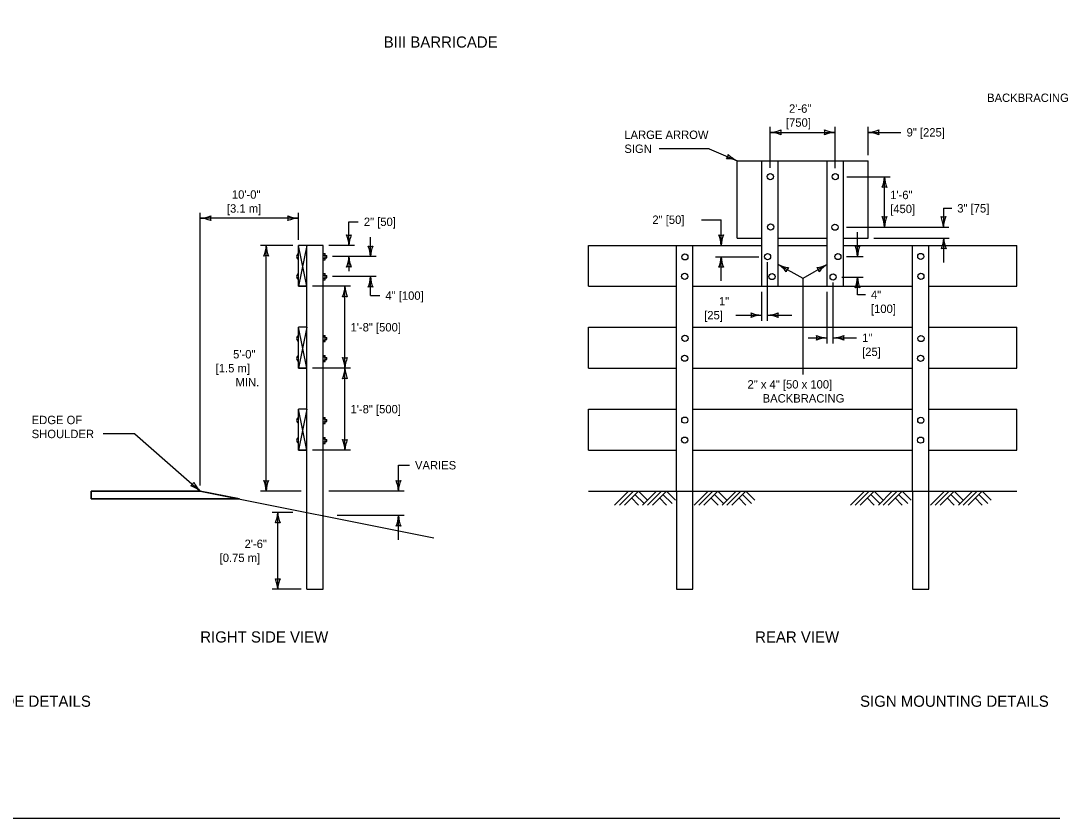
# Model space of a CAD drawing. Extents: x 49991.4 to 50021, y 49987.6 to 50011.4.
# Drawn here: x 50003.93 to 50011.31, y 49987.8 to 49993.51 of the extents above; entities that cross this region are included whole.
import ezdxf

# ---------------------------------------------------------------- set-up
doc = ezdxf.new("R2010")
doc.units = 0
for name, color, linetype in [('Level 1', 7, 'Continuous'), ('Level 2', 7, 'Continuous'), ('Level 3', 7, 'Continuous'), ('Level 4', 7, 'Continuous')]:
    doc.layers.add(name, color=color, linetype=linetype)

msp = doc.modelspace()

# ---------------------------------------------------------------- linework, layer by layer
at = {"layer": 'Level 1'}
for p, q in [((50009.0542, 49992.5038), (50009.9916, 49992.5038)), ((50009.0542, 49991.95), (50009.0542, 49992.5038)), ((50009.2301, 49991.6053), (50009.2301, 49992.5038)), ((50009.3472, 49991.6053), (50009.3472, 49992.5038)), ((50009.6988, 49991.6053), (50009.6988, 49992.5038)), ((50009.8159, 49991.6053), (50009.8159, 49992.5038)), ((50009.9916, 49991.95), (50009.9916, 49992.5038)), ((50009.0542, 49991.95), (50009.2301, 49991.95)), ((50009.3472, 49991.95), (50009.6988, 49991.95)), ((50009.8159, 49991.95), (50009.9916, 49991.95)), ((50005.919, 49991.6053), (50005.919, 49991.8982)), ((50005.9778, 49991.6053), (50005.919, 49991.8982)), ((50005.9778, 49991.8982), (50005.919, 49991.6053)), ((50006.0949, 49991.8982), (50005.919, 49991.8982)), ((50005.9778, 49989.9884), (50005.9778, 49991.8982)), ((50006.0949, 49989.9649), (50006.0949, 49991.8982)), ((50007.991, 49991.8982), (50009.2301, 49991.8982)), ((50007.991, 49991.6053), (50007.991, 49991.8982)), ((50008.6205, 49990.1408), (50008.6205, 49991.8982)), ((50008.7376, 49990.1408), (50008.7376, 49991.8982)), ((50009.3472, 49991.8982), (50009.6988, 49991.8982)), ((50009.8159, 49991.8982), (50011.0547, 49991.8982)), ((50010.308, 49990.1408), (50010.308, 49991.8982)), ((50010.4251, 49990.1408), (50010.4251, 49991.8982)), ((50011.0547, 49991.6053), (50011.0547, 49991.8982)), ((50006.0949, 49991.8397), (50006.1099, 49991.8397)), ((50006.0949, 49991.8287), (50006.1099, 49991.8287)), ((50006.0949, 49991.8067), (50006.1099, 49991.8067)), ((50006.1099, 49991.7957), (50006.1099, 49991.8397)), ((50006.1099, 49991.8252), (50006.1213, 49991.8252)), ((50006.1099, 49991.8102), (50006.1213, 49991.8102)), ((50006.1213, 49991.8102), (50006.1213, 49991.8252)), ((50006.0949, 49991.7957), (50006.1099, 49991.7957)), ((50006.0949, 49991.6966), (50006.1099, 49991.6966)), ((50006.0949, 49991.6856), (50006.1099, 49991.6856)), ((50006.0949, 49991.6636), (50006.1099, 49991.6636)), ((50006.1099, 49991.6526), (50006.1099, 49991.6966)), ((50006.1099, 49991.6821), (50006.1213, 49991.6821)), ((50006.1099, 49991.6671), (50006.1213, 49991.6671)), ((50006.1213, 49991.6671), (50006.1213, 49991.6821)), ((50005.919, 49991.6053), (50005.9778, 49991.6053)), ((50005.9778, 49991.6053), (50005.919, 49991.6053)), ((50006.0949, 49991.6526), (50006.1099, 49991.6526)), ((50007.991, 49991.6053), (50008.6205, 49991.6053)), ((50008.7376, 49991.6053), (50010.308, 49991.6053)), ((50010.4251, 49991.6053), (50011.0547, 49991.6053)), ((50005.919, 49991.0195), (50005.919, 49991.3124)), ((50005.9778, 49991.0195), (50005.919, 49991.3124)), ((50005.9778, 49991.3124), (50005.919, 49991.0195)), ((50005.9778, 49991.3124), (50005.919, 49991.3124)), ((50007.991, 49991.3124), (50008.6205, 49991.3124)), ((50007.991, 49991.0195), (50007.991, 49991.3124)), ((50008.7376, 49991.3124), (50010.308, 49991.3124)), ((50010.4251, 49991.3124), (50011.0547, 49991.3124)), ((50011.0547, 49991.0195), (50011.0547, 49991.3124)), ((50006.0949, 49991.2539), (50006.1099, 49991.2539)), ((50006.0949, 49991.2429), (50006.1099, 49991.2429)), ((50006.0949, 49991.2209), (50006.1099, 49991.2209)), ((50006.1099, 49991.2099), (50006.1099, 49991.2539)), ((50006.1099, 49991.2394), (50006.1213, 49991.2394)), ((50006.1099, 49991.2244), (50006.1213, 49991.2244)), ((50006.1213, 49991.2244), (50006.1213, 49991.2394)), ((50006.0949, 49991.2099), (50006.1099, 49991.2099)), ((50006.0949, 49991.1108), (50006.1099, 49991.1108)), ((50006.0949, 49991.0998), (50006.1099, 49991.0998)), ((50006.0949, 49991.0778), (50006.1099, 49991.0778)), ((50006.0949, 49991.0668), (50006.1099, 49991.0668)), ((50006.1099, 49991.0668), (50006.1099, 49991.1108)), ((50006.1099, 49991.0963), (50006.1213, 49991.0963)), ((50006.1099, 49991.0813), (50006.1213, 49991.0813)), ((50006.1213, 49991.0813), (50006.1213, 49991.0963)), ((50005.919, 49991.0195), (50005.9778, 49991.0195)), ((50005.9778, 49991.0195), (50005.919, 49991.0195)), ((50007.991, 49991.0195), (50008.6205, 49991.0195)), ((50008.7376, 49991.0195), (50010.308, 49991.0195)), ((50010.4251, 49991.0195), (50011.0547, 49991.0195)), ((50005.919, 49990.4336), (50005.919, 49990.7265)), ((50005.9778, 49990.4336), (50005.919, 49990.7265)), ((50005.9778, 49990.7265), (50005.919, 49990.4336)), ((50005.9778, 49990.7265), (50005.919, 49990.7265)), ((50007.991, 49990.7265), (50008.6205, 49990.7265)), ((50007.991, 49990.4336), (50007.991, 49990.7265)), ((50008.7376, 49990.7265), (50010.308, 49990.7265)), ((50010.4251, 49990.7265), (50011.0547, 49990.7265)), ((50011.0547, 49990.4336), (50011.0547, 49990.7265)), ((50006.0949, 49990.668), (50006.1099, 49990.668)), ((50006.0949, 49990.657), (50006.1099, 49990.657)), ((50006.0949, 49990.635), (50006.1099, 49990.635)), ((50006.0949, 49990.624), (50006.1099, 49990.624)), ((50006.1099, 49990.624), (50006.1099, 49990.668)), ((50006.1099, 49990.6535), (50006.1213, 49990.6535)), ((50006.1099, 49990.6385), (50006.1213, 49990.6385)), ((50006.1213, 49990.6385), (50006.1213, 49990.6535)), ((50006.0949, 49990.5249), (50006.1099, 49990.5249)), ((50006.0949, 49990.5139), (50006.1099, 49990.5139)), ((50006.0949, 49990.4919), (50006.1099, 49990.4919)), ((50006.0949, 49990.4809), (50006.1099, 49990.4809)), ((50006.1099, 49990.4809), (50006.1099, 49990.5249)), ((50006.1099, 49990.5104), (50006.1213, 49990.5104)), ((50006.1099, 49990.4954), (50006.1213, 49990.4954)), ((50006.1213, 49990.4954), (50006.1213, 49990.5104)), ((50005.919, 49990.4336), (50005.9778, 49990.4336)), ((50005.9778, 49990.4336), (50005.919, 49990.4336)), ((50007.991, 49990.4336), (50008.6205, 49990.4336)), ((50008.7376, 49990.4336), (50010.308, 49990.4336)), ((50010.4251, 49990.4336), (50011.0547, 49990.4336)), ((50004.4372, 49990.0846), (50004.4372, 49990.1408)), ((50004.4372, 49990.1408), (50005.2159, 49990.1408)), ((50005.2159, 49990.1408), (50004.4372, 49990.1408)), ((50004.4372, 49990.1408), (50004.4372, 49990.0846)), ((50005.2159, 49990.1408), (50006.8865, 49989.8066)), ((50005.4968, 49990.0846), (50005.2159, 49990.1408)), ((50007.991, 49990.1408), (50011.0547, 49990.1408)), ((50008.1785, 49990.0408), (50008.2785, 49990.1408)), ((50008.2135, 49990.0408), (50008.3135, 49990.1408)), ((50008.2485, 49990.0408), (50008.3485, 49990.1408)), ((50008.3238, 49990.1161), (50008.3888, 49990.0511)), ((50008.3485, 49990.1408), (50008.4135, 49990.0758)), ((50008.3785, 49990.0408), (50008.4785, 49990.1408)), ((50008.4135, 49990.0408), (50008.5135, 49990.1408)), ((50008.4485, 49990.0408), (50008.5485, 49990.1408)), ((50008.5238, 49990.1161), (50008.5888, 49990.0511)), ((50008.5485, 49990.1408), (50008.6135, 49990.0758)), ((50008.7466, 49990.0408), (50008.8466, 49990.1408)), ((50008.7816, 49990.0408), (50008.8816, 49990.1408)), ((50008.8166, 49990.0408), (50008.9166, 49990.1408)), ((50008.8919, 49990.1161), (50008.9569, 49990.0511)), ((50008.9166, 49990.1408), (50008.9816, 49990.0758)), ((50008.9466, 49990.0408), (50009.0466, 49990.1408)), ((50008.9816, 49990.0408), (50009.0816, 49990.1408)), ((50009.0166, 49990.0408), (50009.1166, 49990.1408)), ((50009.0919, 49990.1161), (50009.1569, 49990.0511)), ((50009.1166, 49990.1408), (50009.1816, 49990.0758)), ((50009.8639, 49990.0408), (50009.9639, 49990.1408)), ((50009.8989, 49990.0408), (50009.9989, 49990.1408)), ((50009.9339, 49990.0408), (50010.0339, 49990.1408)), ((50010.0092, 49990.1161), (50010.0742, 49990.0511)), ((50010.0339, 49990.1408), (50010.0989, 49990.0758)), ((50010.0639, 49990.0408), (50010.1639, 49990.1408)), ((50010.0989, 49990.0408), (50010.1989, 49990.1408)), ((50010.1339, 49990.0408), (50010.2339, 49990.1408)), ((50010.2092, 49990.1161), (50010.2742, 49990.0511)), ((50010.2339, 49990.1408), (50010.2989, 49990.0758)), ((50010.4361, 49990.0408), (50010.5361, 49990.1408)), ((50010.4711, 49990.0408), (50010.5711, 49990.1408)), ((50010.5061, 49990.0408), (50010.6061, 49990.1408)), ((50010.5814, 49990.1161), (50010.6464, 49990.0511)), ((50010.6061, 49990.1408), (50010.6711, 49990.0758)), ((50010.6361, 49990.0408), (50010.7361, 49990.1408)), ((50010.6711, 49990.0408), (50010.7711, 49990.1408)), ((50010.7061, 49990.0408), (50010.8061, 49990.1408)), ((50010.7814, 49990.1161), (50010.8464, 49990.0511)), ((50010.8061, 49990.1408), (50010.8711, 49990.0758)), ((50005.4968, 49990.0846), (50004.4372, 49990.0846)), ((50004.4372, 49990.0846), (50005.4968, 49990.0846)), ((50005.4968, 49990.0846), (50005.4968, 49990.0846)), ((50008.299, 49990.0913), (50008.3495, 49990.0408)), ((50008.499, 49990.0913), (50008.5495, 49990.0408)), ((50008.8671, 49990.0913), (50008.9176, 49990.0408)), ((50009.0671, 49990.0913), (50009.1176, 49990.0408)), ((50009.9844, 49990.0913), (50010.0349, 49990.0408)), ((50010.1844, 49990.0913), (50010.2349, 49990.0408)), ((50010.5566, 49990.0913), (50010.6071, 49990.0408)), ((50010.7566, 49990.0913), (50010.8071, 49990.0408))]:
    msp.add_line(p, q, dxfattribs=at)
msp.add_lwpolyline([(49999.3835, 49998.9992), (50016.7501, 49998.9992), (50016.7501, 49987.7988), (49999.3835, 49987.7988)], close=True, dxfattribs=at)
for centre in [(50009.2915, 49992.3902), (50009.7557, 49992.3896), (50009.2939, 49992.0303), (50009.7539, 49992.0285), (50008.6808, 49991.8158), (50009.2721, 49991.8173), (50009.7749, 49991.8185), (50010.3674, 49991.8188), (50008.6795, 49991.6763), (50009.3037, 49991.6752), (50009.7405, 49991.6716), (50010.368, 49991.6763), (50008.6813, 49991.2331), (50010.3686, 49991.2319), (50008.6789, 49991.0907), (50010.3662, 49991.0901), (50008.6804, 49990.6478), (50010.3677, 49990.6472), (50008.6798, 49990.5053), (50010.3659, 49990.5047)]:
    msp.add_circle(centre, 0.022, dxfattribs=at)
for centre in [(50005.9287, 49991.8182), (50005.9287, 49991.6752), (50005.9287, 49991.2324), (50005.9287, 49991.0894), (50005.9287, 49990.6465), (50005.9287, 49990.5035)]:
    msp.add_arc(centre, 0.0243, 113.46993, 246.53007, dxfattribs=at)
at = {"layer": 'Level 3'}
for p, q in [((50009.2915, 49992.4522), (50009.2915, 49992.747)), ((50009.2915, 49992.707), (50009.7557, 49992.707)), ((50009.7557, 49992.4516), (50009.7557, 49992.747)), ((50009.9916, 49992.5438), (50009.9916, 49992.747)), ((50009.9916, 49992.707), (50010.2259, 49992.707)), ((50008.854, 49992.5896), (50008.4966, 49992.5896)), ((50008.854, 49992.5896), (50009.0542, 49992.5038)), ((50009.8377, 49992.3896), (50010.1484, 49992.3896)), ((50010.1084, 49992.0285), (50010.1084, 49992.3896)), ((50005.2159, 49990.1808), (50005.2159, 49992.1323)), ((50005.919, 49991.9382), (50005.919, 49992.1323)), ((50010.5288, 49992.1635), (50010.5288, 49992.0285)), ((50010.5288, 49992.1635), (50010.5882, 49992.1635)), ((50005.919, 49992.0923), (50005.2159, 49992.0923)), ((50006.2789, 49991.8982), (50006.2789, 49992.067)), ((50006.2789, 49992.067), (50006.3455, 49992.067)), ((50008.7995, 49992.0818), (50008.94, 49992.0818)), ((50008.94, 49991.8982), (50008.94, 49992.0818)), ((50009.8359, 49992.0285), (50010.5688, 49992.0285)), ((50006.4331, 49991.8177), (50006.4331, 49991.9567)), ((50009.9151, 49991.8185), (50009.9151, 49991.9919)), ((50010.0316, 49991.95), (50010.5715, 49991.95)), ((50010.5315, 49991.7766), (50010.5315, 49991.95)), ((50005.879, 49991.8982), (50005.6477, 49991.8982)), ((50005.6877, 49990.1408), (50005.6877, 49991.8982)), ((50006.3189, 49991.8982), (50006.1349, 49991.8982)), ((50006.4731, 49991.8177), (50006.1613, 49991.8177)), ((50006.2789, 49991.8177), (50006.2789, 49991.7146)), ((50008.9, 49991.8173), (50009.2101, 49991.8173)), ((50008.94, 49991.6439), (50008.94, 49991.8173)), ((50009.8369, 49991.8185), (50009.9551, 49991.8185)), ((50009.2721, 49991.3591), (50009.2721, 49991.7773)), ((50009.3472, 49991.7621), (50009.523, 49991.663)), ((50009.6988, 49991.7621), (50009.523, 49991.6622)), ((50006.4731, 49991.6746), (50006.1613, 49991.6746)), ((50006.4331, 49991.539), (50006.4331, 49991.6746)), ((50009.523, 49991.663), (50009.523, 49990.9739)), ((50009.8024, 49991.6716), (50009.9551, 49991.6716)), ((50009.9151, 49991.5447), (50009.9151, 49991.6716)), ((50006.2904, 49991.6053), (50006.0178, 49991.6053)), ((50006.2504, 49991.0195), (50006.2504, 49991.6053)), ((50009.7405, 49991.1966), (50009.7405, 49991.6316)), ((50006.4331, 49991.539), (50006.4997, 49991.539)), ((50009.2301, 49991.3591), (50009.2301, 49991.5653)), ((50009.6988, 49991.1966), (50009.6988, 49991.5653)), ((50009.9712, 49991.5447), (50009.9151, 49991.5447)), ((50009.0454, 49991.3991), (50009.2301, 49991.3991)), ((50009.2721, 49991.3991), (50009.4455, 49991.3991)), ((50009.563, 49991.2366), (50009.6988, 49991.2366)), ((50009.7405, 49991.2366), (50009.9079, 49991.2366)), ((50006.2904, 49991.0195), (50006.0178, 49991.0195)), ((50006.2504, 49990.4336), (50006.2504, 49991.0195)), ((50004.7473, 49990.5492), (50004.5211, 49990.5492)), ((50004.7473, 49990.5492), (50005.2159, 49990.1408)), ((50006.2904, 49990.4336), (50006.0178, 49990.4336)), ((50006.6327, 49990.1408), (50006.6327, 49990.3254)), ((50006.6327, 49990.3254), (50006.7112, 49990.3254)), ((50005.9378, 49990.1408), (50005.6477, 49990.1408)), ((50006.6727, 49990.1408), (50006.1349, 49990.1408)), ((50005.8778, 49989.9882), (50005.7297, 49989.9882)), ((50005.7697, 49989.4376), (50005.7697, 49989.9882)), ((50006.673, 49989.9649), (50006.1949, 49989.9649)), ((50006.633, 49989.7915), (50006.633, 49989.9649)), ((50005.9378, 49989.4376), (50005.7297, 49989.4376))]:
    msp.add_line(p, q, dxfattribs=at)
for centre, radius, start, end in [((50009.2801, 49992.9397), 0.233, 272.82731, 292.07716), ((50009.2824, 49992.4849), 0.2223, 67.45601, 87.63952), ((50009.4198, 49992.707), 0.0548, 162.13882, 197.86118), ((50009.7649, 49992.9291), 0.2223, 247.45601, 267.63952), ((50009.6275, 49992.707), 0.0548, 342.13882, 17.86118), ((50009.7672, 49992.4743), 0.233, 92.82731, 112.07716), ((50009.9801, 49992.9397), 0.233, 272.82731, 292.07716), ((50009.9824, 49992.4849), 0.2223, 67.45601, 87.63952), ((50010.1198, 49992.707), 0.0548, 162.13882, 197.86118), ((50008.9364, 49992.5543), 0.0548, 318.94023, 354.66259), ((50009.1501, 49992.7044), 0.2223, 224.25742, 244.44093), ((50008.9731, 49992.2854), 0.233, 69.62872, 88.87857), ((50009.8863, 49992.3988), 0.2223, 337.45601, 357.63952), ((50010.3411, 49992.4011), 0.233, 182.82731, 202.07716), ((50010.1084, 49992.2614), 0.0548, 72.13882, 107.86118), ((50005.2044, 49992.325), 0.233, 272.82731, 292.07716), ((50005.3441, 49992.0923), 0.0548, 162.13882, 197.86118), ((50005.9282, 49992.3144), 0.2223, 247.45601, 267.63952), ((50005.7908, 49992.0923), 0.0548, 342.13882, 17.86118), ((50010.1084, 49992.1567), 0.0548, 252.13882, 287.86118), ((50009.8757, 49992.017), 0.233, 2.82731, 22.07716), ((50010.3305, 49992.0193), 0.2223, 157.45601, 177.63952), ((50010.5288, 49992.1567), 0.0548, 252.13882, 287.86118), ((50010.2961, 49992.017), 0.233, 2.82731, 22.07716), ((50010.7509, 49992.0193), 0.2223, 157.45601, 177.63952), ((50005.2067, 49991.8702), 0.2223, 67.45601, 87.63952), ((50005.9305, 49991.8596), 0.233, 92.82731, 112.07716), ((50006.2789, 49992.0264), 0.0548, 252.13882, 287.86118), ((50006.0462, 49991.8867), 0.233, 2.82731, 22.07716), ((50006.501, 49991.889), 0.2223, 157.45601, 177.63952), ((50008.94, 49992.0264), 0.0548, 252.13882, 287.86118), ((50008.7073, 49991.8867), 0.233, 2.82731, 22.07716), ((50009.1621, 49991.889), 0.2223, 157.45601, 177.63952), ((50010.3094, 49991.9592), 0.2223, 337.45601, 357.63952), ((50010.7642, 49991.9615), 0.233, 182.82731, 202.07716), ((50005.4656, 49991.9074), 0.2223, 337.45601, 357.63952), ((50005.9204, 49991.9097), 0.233, 182.82731, 202.07716), ((50006.4331, 49991.9459), 0.0548, 252.13882, 287.86118), ((50006.2004, 49991.8062), 0.233, 2.82731, 22.07716), ((50006.6552, 49991.8085), 0.2223, 157.45601, 177.63952), ((50009.9151, 49991.9467), 0.0548, 252.13882, 287.86118), ((50009.6824, 49991.807), 0.233, 2.82731, 22.07716), ((50010.1372, 49991.8093), 0.2223, 157.45601, 177.63952), ((50010.5315, 49991.8218), 0.0548, 72.13882, 107.86118), ((50005.6877, 49991.77), 0.0548, 72.13882, 107.86118), ((50006.0568, 49991.8269), 0.2223, 337.45601, 357.63952), ((50006.5116, 49991.8292), 0.233, 182.82731, 202.07716), ((50008.7179, 49991.8265), 0.2223, 337.45601, 357.63952), ((50009.1727, 49991.8288), 0.233, 182.82731, 202.07716), ((50006.2789, 49991.6895), 0.0548, 72.13882, 107.86118), ((50008.94, 49991.6891), 0.0548, 72.13882, 107.86118), ((50009.2301, 49991.5731), 0.2223, 38.04568, 58.22918), ((50009.4515, 49991.9705), 0.233, 243.41698, 262.66683), ((50009.4589, 49991.6991), 0.0548, 132.72848, 168.45084), ((50009.597, 49991.9598), 0.2223, 277.06382, 297.24733), ((50009.5873, 49991.6988), 0.0548, 11.74663, 47.46899), ((50009.8238, 49991.5655), 0.233, 122.43512, 141.68497), ((50006.211, 49991.6838), 0.2223, 337.45601, 357.63952), ((50006.6658, 49991.6861), 0.233, 182.82731, 202.07716), ((50009.693, 49991.6808), 0.2223, 337.45601, 357.63952), ((50010.1478, 49991.6831), 0.233, 182.82731, 202.07716), ((50006.0283, 49991.6145), 0.2223, 337.45601, 357.63952), ((50006.4831, 49991.6168), 0.233, 182.82731, 202.07716), ((50006.4331, 49991.5464), 0.0548, 72.13882, 107.86118), ((50009.9151, 49991.5434), 0.0548, 72.13882, 107.86118), ((50006.2504, 49991.4771), 0.0548, 72.13882, 107.86118), ((50009.2393, 49991.6212), 0.2223, 247.45601, 267.63952), ((50009.1019, 49991.3991), 0.0548, 342.13882, 17.86118), ((50009.2416, 49991.1664), 0.233, 92.82731, 112.07716), ((50009.2606, 49991.6318), 0.233, 272.82731, 292.07716), ((50009.2629, 49991.177), 0.2223, 67.45601, 87.63952), ((50009.4003, 49991.3991), 0.0548, 162.13882, 197.86118), ((50009.708, 49991.4587), 0.2223, 247.45601, 267.63952), ((50009.5706, 49991.2366), 0.0548, 342.13882, 17.86118), ((50009.7103, 49991.0039), 0.233, 92.82731, 112.07716), ((50009.729, 49991.4693), 0.233, 272.82731, 292.07716), ((50009.7313, 49991.0145), 0.2223, 67.45601, 87.63952), ((50009.8687, 49991.2366), 0.0548, 162.13882, 197.86118), ((50006.2504, 49991.1477), 0.0548, 252.13882, 287.86118), ((50006.0177, 49991.008), 0.233, 2.82731, 22.07716), ((50006.4725, 49991.0103), 0.2223, 157.45601, 177.63952), ((50006.0283, 49991.0287), 0.2223, 337.45601, 357.63952), ((50006.4831, 49991.031), 0.233, 182.82731, 202.07716), ((50006.2504, 49990.8913), 0.0548, 72.13882, 107.86118), ((50006.2504, 49990.5618), 0.0548, 252.13882, 287.86118), ((50006.0177, 49990.4221), 0.233, 2.82731, 22.07716), ((50006.4725, 49990.4244), 0.2223, 157.45601, 177.63952), ((50005.1192, 49990.225), 0.0548, 301.06308, 336.78544), ((50005.3688, 49990.3022), 0.2223, 206.38027, 226.56378), ((50005.6877, 49990.269), 0.0548, 252.13882, 287.86118), ((50005.455, 49990.1293), 0.233, 2.82731, 22.07716), ((50005.9098, 49990.1316), 0.2223, 157.45601, 177.63952), ((50006.6327, 49990.269), 0.0548, 252.13882, 287.86118), ((50006.4, 49990.1293), 0.233, 2.82731, 22.07716), ((50006.8548, 49990.1316), 0.2223, 157.45601, 177.63952), ((50005.0717, 49989.9578), 0.233, 51.75157, 71.00142), ((50005.5476, 49989.9974), 0.2223, 337.45601, 357.63952), ((50006.0024, 49989.9997), 0.233, 182.82731, 202.07716), ((50006.4109, 49989.9741), 0.2223, 337.45601, 357.63952), ((50006.8657, 49989.9764), 0.233, 182.82731, 202.07716), ((50005.7697, 49989.86), 0.0548, 72.13882, 107.86118), ((50006.633, 49989.8367), 0.0548, 72.13882, 107.86118), ((50005.7697, 49989.5658), 0.0548, 252.13882, 287.86118), ((50005.537, 49989.4261), 0.233, 2.82731, 22.07716), ((50005.9918, 49989.4284), 0.2223, 157.45601, 177.63952)]:
    msp.add_arc(centre, radius, start, end, dxfattribs=at)
at = {"layer": 'Level 4'}
for p, q in [((50008.6205, 49990.1408), (50008.6205, 49989.4376)), ((50008.7376, 49989.4376), (50008.7376, 49990.1408)), ((50010.308, 49990.1408), (50010.308, 49989.4376)), ((50010.4251, 49989.4376), (50010.4251, 49990.1408)), ((50005.9778, 49989.4376), (50005.9778, 49989.9884)), ((50006.0949, 49989.4376), (50006.0949, 49989.9649)), ((50005.9778, 49989.4376), (50006.0949, 49989.4376)), ((50008.6205, 49989.4376), (50008.7376, 49989.4376)), ((50010.308, 49989.4376), (50010.4251, 49989.4376))]:
    msp.add_line(p, q, dxfattribs=at)

# ---------------------------------------------------------------- texts
at = {"layer": 'Level 2'}
for s, height, p in [('BIII BARRICADE', 0.08, (50006.5276, 49993.3131)), ('BACKBRACING', 0.06, (50010.8416, 49992.9243)), ('2\'-6"', 0.06, (50009.4253, 49992.847)), ('[750]', 0.06, (50009.4035, 49992.747)), ('LARGE ARROW', 0.06, (50008.2479, 49992.6596)), ('9" [225]', 0.06, (50010.2659, 49992.677)), ('SIGN', 0.06, (50008.2479, 49992.5596)), ('10\'-0"', 0.06, (50005.442, 49992.2323)), ('1\'-6"', 0.06, (50010.1484, 49992.2291)), ('[3.1 m]', 0.06, (50005.4067, 49992.1323)), ('[450]', 0.06, (50010.1484, 49992.1291)), ('3" [75]', 0.06, (50010.6282, 49992.1335)), ('2" [50]', 0.06, (50006.3855, 49992.037)), ('2" [50]', 0.06, (50008.4484, 49992.0518)), ('4" [100]', 0.06, (50006.5397, 49991.509)), ('1"', 0.06, (50008.9247, 49991.4691)), ('4"', 0.06, (50010.0112, 49991.5147)), ('[100]', 0.06, (50010.0112, 49991.4147)), ('[25]', 0.06, (50008.8188, 49991.3691)), ('1\'-8" [500]', 0.06, (50006.2904, 49991.2824)), ('1"', 0.06, (50009.9479, 49991.2066)), ('5\'-0"', 0.06, (50005.4508, 49991.0895)), ('[25]', 0.06, (50009.9479, 49991.1066)), ('[1.5 m]', 0.06, (50005.3263, 49990.9895)), ('MIN.', 0.06, (50005.4681, 49990.8895)), ('2" x 4" [50 x 100]', 0.06, (50009.1285, 49990.8739)), ('BACKBRACING', 0.06, (50009.2368, 49990.7739)), ('1\'-8" [500]', 0.06, (50006.2904, 49990.6966)), ('EDGE OF', 0.06, (50004.0108, 49990.6192)), ('SHOULDER', 0.06, (50004.0108, 49990.5192)), ('VARIES', 0.06, (50006.7512, 49990.2954)), ('2\'-6"', 0.06, (50005.5328, 49989.7329)), ('[0.75 m]', 0.06, (50005.3545, 49989.6329)), ('RIGHT SIDE VIEW', 0.08, (50005.2159, 49989.0568)), ('REAR VIEW', 0.08, (50009.1831, 49989.0568)), ('BARRICADE DETAILS', 0.08, (50003.3342, 49988.5972)), ('SIGN MOUNTING DETAILS', 0.08, (50009.9333, 49988.5972))]:
    msp.add_text(s, height=height, dxfattribs=at).set_placement(p)

doc.saveas('drawing.dxf')
